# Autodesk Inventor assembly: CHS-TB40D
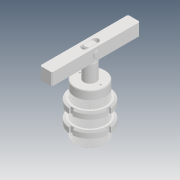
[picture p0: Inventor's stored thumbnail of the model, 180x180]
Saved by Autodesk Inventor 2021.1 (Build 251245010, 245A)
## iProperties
Created: 2019-04
Part Number: CHS-TB40D
Description: STEP AP203
Document SubType Name: Assembly
Designer: user
Title: chs-tb40d_asm.STEP
Revision Number: ÈÎºÎ
Sending System: SolidWorks 2017
Preprocessor: SwSTEP 2.0
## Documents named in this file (7)
- D:\Vault_2016\Projekty\Clamptek\Hydraulic\CHS\CHS-40\Inventor\CHS-TB40D\CHS-TB40D.iam
- D:\Vault_2016\Projekty\Clamptek\Hydraulic\CHS\CHS-40\Inventor\CHS-TB40D\CHS-TB40-03.ipt
- D:\Vault_2016\Projekty\Clamptek\Hydraulic\CHS\CHS-40\Inventor\CHS-TB40D\CHS-TB40-04.ipt
- D:\Vault_2016\Projekty\Clamptek\Hydraulic\CHS\CHS-40\Inventor\CHS-TB40D\CHS-40D-02_5.ipt
- D:\Vault_2016\Projekty\Clamptek\Hydraulic\CHS\CHS-40\Inventor\CHS-TB40D\CHS-40D-01_6.ipt
- D:\Vault_2016\Projekty\Clamptek\Hydraulic\CHS\CHS-40\Inventor\CHS-TB40D\XIAO.ipt
- D:\Vault_2016\Projekty\Clamptek\Hydraulic\CHS\CHS-40\Inventor\CHS-TB40D\12ÖáÓÃµ²È¦.ipt
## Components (8 placed, 8 different names)
1. CHS-TB40-03_1
2. CHS-TB40-04_2
3. CHS-TB40-04_3
4. CHS-40D-02_5_4
5. CHS-40D-01_6_5
6. XIAO_6
7. 12ÖáÓÃµ²È¦_7
8. 12ÖáÓÃµ²È¦_8
